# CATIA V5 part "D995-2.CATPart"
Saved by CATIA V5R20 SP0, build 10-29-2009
Part number: D995-2
Source: Unknown
Property "ARTICLENO": "D995-2"
Property "BOMINFO": "D995-2"
Property "CODE": "D995-2"
Property "F1": "50.000"
Property "F2": "68.000"
Property "L": "274.000"
Property "L1": "200.000"
Property "L2": "135.000"
Property "L3": "145.000"
Property "LINA": "D995-2"
Property "NB": "D995-2"
Property "NBSYN": "$CODE."
Property "NN": "D995"
Property "NT": "D995"
Property "S": "65.000"
Property "SUPPLIER": "CF"
Bounding box of the stored display mesh (mm): x -22.5 to 22.5, y -291 to 0, z -22.5 to 22.5
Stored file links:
  C:\Users\Utente\Desktop\3D files D995\D995-2.CATPart
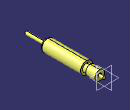
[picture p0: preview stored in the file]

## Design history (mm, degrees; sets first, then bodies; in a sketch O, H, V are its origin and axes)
Body1 "Geometry.1" (main body)
  Solid1 "D995-2.catpart": solid without history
